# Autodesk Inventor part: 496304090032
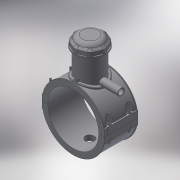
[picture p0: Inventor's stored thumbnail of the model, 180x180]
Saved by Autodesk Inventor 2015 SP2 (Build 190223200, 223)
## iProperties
Created: 2017-07
Part Number: 496304090032
Material: Generic
Description: PLASSON TAPPING SADDLE 90x32
Document SubType Name: Modeling
Designer: KIM
Mass: 588.615 g
Surface Area: 1522.59 cm^2
Volume: 588.615 cm^3
Density: 1 g/cm^3
Appearance: Default
Author: KIM
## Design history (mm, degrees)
derived "496304.ipt"
feature "Solid1::496304.ipt"
feature "Solid2::496304.ipt"
feature "Solid4::496304.ipt"
feature "Solid5::496304.ipt"
tag "TaggingFeature1"
body "Solid1"
body "Solid2"
other parameters: "d2" = 126, "d3" = 22.5, "d4" = 118, "d5" = 0, "d6" = 0.1, "d8" = 0, "d19" = 6, "d20" = 6, "d21" = 70.8, "d23" = 0, "d24" = 35.4, "d26" = 0, "d29" = 3, "d31" = 6, "d32" = 0, "d33" = 0, "d34" = 0.6, "d40" = 58.032, "d41" = 63, "d43" = 0, "d45" = 0, "d47" = 126.6, "d70" = 15, "d72" = 0, "d73" = 6, "d75" = 5, "d76" = 0, "d77" = 4.5, "d78" = 75, "d79" = 15, "d80" = 47.2, "d82" = 5 deg, "d84" = 4, "d85" = 14, "d86" = 0, "d87" = 3, "d88" = 0, "d89" = 1, "d90" = 1, "d91" = 94.4, "d92" = 0, "d93" = 0.5, "d94" = 47.36842, "d96" = 113.832, "d97" = 2.36, "d98" = 0, "d102" = 0.9, "d120" = 140 deg, "d121" = 24.228, "d122" = 20 deg, "d123" = 223.2, "d124" = 66.96, "d126" = 0, "d143" = 92.7, "d145" = 16.61538, "d149" = 1.35, "d150" = 18.27692, "d153" = 118, "d154" = 0, "d156" = 55.8, "d157" = 160 deg, "d159" = 4.32, "d161" = 1.35, "d162" = 70.8, "d163" = 0, "d164" = 45, "d167" = 9, "d168" = 54.43902, "d170" = 3.375, "d172" = 0, "d173" = 1, "d175" = 45, "d176" = 20 deg, "d177" = 6.3, "d178" = 21.6, "d180" = 0, "d183" = 8.64, "d184" = 5.04, "d185" = 38.35, "d186" = 38.35, "d187" = 55.8, "d188" = 6.48, "d189" = 6.3, "d190" = 0, "d191" = 83.7, "d193" = 6.3, "d194" = 4.13, "d195" = 90 deg, "d197" = 0, "d199" = 0, "d200" = 10.8, "d202" = 0, "d203" = 114, "d204" = 59.85, "d205" = 44.1, "d206" = 53.55, "d207" = 85.5, "d208" = 88.92, "d209" = 106.02, "d210" = 54.18, "d211" = 63, "d212" = 50.4, "d213" = 0, "d216" = 0, "d217" = 9, "d218" = 9, "d219" = 1.8, "d224" = 0, "d230" = 5.4, "d233" = 6, "d236" = 63, "d237" = 35.4, "d238" = 6.02433, "d240" = 35.4, "d241" = 35.4, "d242" = 35.4, "d243" = 6, "d244" = 35.4, "d245" = 35.4, "d246" = 35.4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
